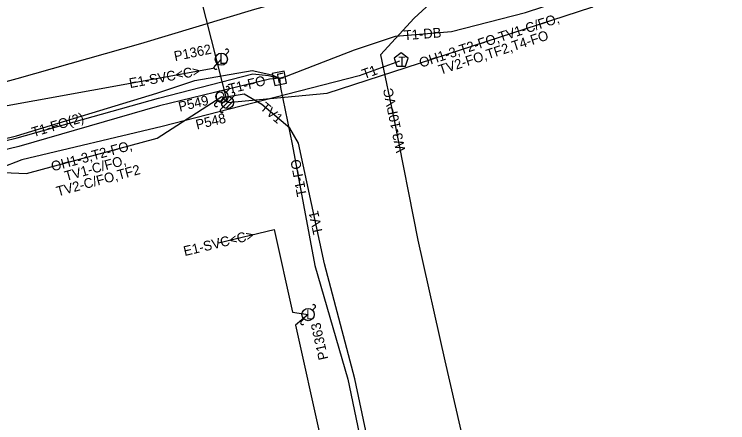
# Model space of a CAD drawing. Extents: x 2336688 to 2352634, y 362473 to 369571.
# Drawn here: x 2348250.9 to 2348543.2, y 367383.7 to 367551 of the extents above; entities that cross this region are included whole.
import ezdxf

# ---------------------------------------------------------------- set-up
doc = ezdxf.new("R2010")
doc.units = 0
for name, color, linetype in [('RD_EX_DV_Prop', 7, 'Continuous'), ('RD_EX_DV_TX_Prop', 7, 'Continuous'), ('RD_EX_RW', 7, 'Continuous'), ('RD_EX_RW_TX', 7, 'Continuous'), ('RD_HC_Data_Tic', 7, 'Continuous'), ('RD_PD_CstnLmt', 7, 'Continuous'), ('RD_PD_Final_TrvlWay', 7, 'Continuous'), ('RD_PD_PatLn4', 7, 'Continuous'), ('RD_SHT_ShtClip', 7, 'Continuous'), ('RD_Sketch2', 7, 'Continuous')]:
    doc.layers.add(name, color=color, linetype=linetype)

msp = doc.modelspace()

# ---------------------------------------------------------------- linework, layer by layer
at = {"layer": 'RD_EX_RW_TX'}
for points in [[(2348359.53, 367524.74), (2348362.5, 367525.55), (2348390.35, 367536.41), (2348407.13, 367542.05), (2348430.08, 367543.86), (2348460.37, 367551.68), (2348518.82, 367570.97), (2348539.75, 367577.27)], [(2348408.72, 367531.76), (2348392.21, 367525.78), (2348357.71, 367516.89), (2348311.55, 367505.03), (2348253.93, 367491.37), (2348226.44, 367480.77)], [(2348206.38, 367490.17), (2348251.79, 367501.21), (2348309.34, 367518.63), (2348324.84, 367523.82), (2348348.43, 367527.96), (2348356.39, 367526.21), (2348359.53, 367524.74), (2348359.93, 367520.91), (2348364.81, 367497.75), (2348374.05, 367448.12), (2348387.55, 367401.49), (2348397.52, 367353.79)], [(2348359.53, 367524.74), (2348355.51, 367524.43), (2348310.45, 367513.44), (2348252.78, 367496.75), (2348207.14, 367485.87), (2348156.56, 367475.89), (2348137.31, 367470.75), (2348134.76, 367458.49), (2348133.52, 367438.68), (2348140.76, 367386.86)], [(2348209.5, 367456.28), (2348210.32, 367458.48), (2348208.63, 367474.37), (2348207.08, 367489.5), (2348252.08, 367500.34), (2348310.01, 367516.64), (2348348.6, 367526.57), (2348355.1, 367525.87), (2348359.53, 367524.74)], [(2348400.57, 367353.94), (2348390.4, 367401.66), (2348378.01, 367448.82), (2348367.38, 367498.18), (2348363.76, 367504.36), (2348352.34, 367514.01), (2348345.04, 367518.21), (2348337.62, 367517), (2348338.28, 367514.83)]]:
    msp.add_lwpolyline(points, dxfattribs=at)
for points in [[(2348409.46, 367535.1), (2348406.61, 367533.03), (2348407.7, 367529.68), (2348411.22, 367529.68), (2348412.31, 367533.03)], [(2348361.48, 367527.69), (2348356.58, 367526.68), (2348357.59, 367521.78), (2348362.49, 367522.79)]]:
    msp.add_lwpolyline(points, close=True, dxfattribs=at)
at = {"layer": 'RD_HC_Data_Tic'}
for p, q in [((2348337.5, 367534.34), (2348338.56, 367535.4)), ((2348332.9, 367529.74), (2348333.96, 367530.8)), ((2348338.81, 367520.09), (2348337.75, 367519.02)), ((2348334.22, 367515.49), (2348333.16, 367514.43)), ((2348338.93, 367517.24), (2348335.86, 367514.18)), ((2348340.05, 367516.6), (2348336.51, 367513.06)), ((2348340.69, 367515.48), (2348337.63, 367512.41)), ((2348341.11, 367517.66), (2348340.05, 367516.6)), ((2348336.51, 367513.06), (2348335.45, 367512)), ((2348373.05, 367429.74), (2348374.11, 367430.8)), ((2348368.45, 367425.14), (2348369.51, 367426.2))]:
    msp.add_line(p, q, dxfattribs=at)
for centre in [(2348335.73, 367532.57), (2348335.99, 367517.26), (2348338.28, 367514.83), (2348371.28, 367427.97)]:
    msp.add_circle(centre, 2.5, dxfattribs=at)
for centre, start, end in [((2348338.03, 367535.93), 315, 135), ((2348333.43, 367529.21), 135, 315), ((2348338.28, 367520.62), 315, 135), ((2348340.58, 367518.19), 315, 135), ((2348333.69, 367513.9), 135, 315), ((2348335.98, 367511.47), 135, 315), ((2348373.58, 367431.33), 315, 135), ((2348368.98, 367424.61), 135, 315)]:
    msp.add_arc(centre, 0.75, start, end, dxfattribs=at)
at = {"layer": 'RD_PD_Final_TrvlWay'}
for points in [[(2348085.42, 367455.46), (2348069.9, 367482.21), (2348074.61, 367480.08), (2348206.15, 367506.02), (2348207.03, 367509.26), (2348209.48, 367506.65), (2348332.4, 367528.92), (2348335.73, 367532.57)], [(2348334.56, 367457.38), (2348357.39, 367462.88), (2348364.93, 367428.99), (2348371.28, 367427.97), (2348366.1, 367423.71), (2348386.64, 367331.4), (2348390.5, 367330.62), (2348387.22, 367328.8), (2348383.03, 367308.02)]]:
    msp.add_lwpolyline(points, dxfattribs=at)
at = {"layer": 'RD_SHT_ShtClip'}
for q in [(2348302.69, 367654.16), (2348335.99, 367517.26)]:
    msp.add_line((2348338.28, 367514.83), q, dxfattribs=at)
for points in [[(2348338.28, 367514.83), (2348379.11, 367518.63), (2348487.57, 367553.93), (2348522.81, 367574.9)], [(2348224.48, 367487.16), (2348255.92, 367485.8), (2348309.5, 367500.26), (2348335.99, 367517.26)]]:
    msp.add_lwpolyline(points, dxfattribs=at)
at = {"layer": 'RD_Sketch2'}
for points in [[(2348204.32, 367511.65), (2348252.13, 367524.59), (2348302.77, 367538.93), (2348349.4, 367552.98), (2348399.28, 367566.78), (2348419.19, 367573.03), (2348448.96, 367582.56), (2348495.7, 367596.69), (2348520.67, 367604.71), (2348535.97, 367592.48), (2348556.39, 367599.86), (2348601.65, 367616.49)], [(2348419.19, 367573.03), (2348421.47, 367566.58), (2348424.48, 367558.37), (2348414.74, 367549.36), (2348401.01, 367534.36), (2348406.6, 367507.53), (2348416.22, 367458.49), (2348427.29, 367409.06), (2348435.75, 367372.22)]]:
    msp.add_lwpolyline(points, dxfattribs=at)

# ---------------------------------------------------------------- texts
at = {"layer": 'RD_EX_DV_Prop'}
for rotation, p in [(10.2677, (2348298.33, 367520.71)), (13.57, (2348320.74, 367451.92))]:
    msp.add_text('E1-SVC<C>', height=4, rotation=rotation, dxfattribs=at).set_placement(p)
at = {"layer": 'RD_EX_DV_TX_Prop'}
for s, rotation, p in [('P1362', 11.5862, (2348316.77, 367531.76)), ('P549', 13.4802, (2348318.69, 367511.07)), ('P548', 13.4802, (2348325.76, 367503.73)), ('P1363', 102.542, (2348379.58, 367409.88))]:
    msp.add_text(s, height=4, rotation=rotation, dxfattribs=at).set_placement(p)
at = {"layer": 'RD_EX_RW'}
for s, rotation, p in [('T1-DB', 4.5062, (2348410.64, 367540.32)), ('T1', 19.8997, (2348394.21, 367524.38)), ('T1-FO', 13.7156, (2348339.18, 367518.39)), ('TV1', 319.7902, (2348351.34, 367512.24)), ('T1-FO(2)', 16.8473, (2348258.72, 367500.61)), ('T1-FO', 100.5445, (2348370.77, 367476.69)), ('TV1', 102.1548, (2348377.39, 367461.21))]:
    msp.add_text(s, height=4, rotation=rotation, dxfattribs=at).set_placement(p)
at = {"layer": 'RD_EX_RW_TX'}
msp.add_text('T', height=3.75, dxfattribs=at).set_placement((2348408.23, 367529.88))
msp.add_text('F', height=4, rotation=11.6664, dxfattribs=at).set_placement((2348358.83, 367522.55))
at = {"layer": 'RD_HC_Data_Tic'}
for s, rotation, p in [('L', 360, (2348334.92, 367530.64)), ('O', 180, (2348337.28, 367519.26)), ('L', 360, (2348370.47, 367426.03))]:
    msp.add_text(s, height=4, rotation=rotation, dxfattribs=at).set_placement(p)
at = {"layer": 'RD_PD_CstnLmt'}
msp.add_text('W3-10PVC', height=4, rotation=101.7679, dxfattribs=at).set_placement((2348411.29, 367494.83))
at = {"layer": 'RD_PD_PatLn4'}
for s, rotation, p in [('OH1-3,T2-FO,TV1-C/FO,', 18.0321, (2348417.56, 367529.04)), ('TV2-FO,TF2,T4-FO', 18.0321, (2348425.51, 367526.15)), ('OH1-3,T2-FO,', 15.1654, (2348266.59, 367486.58)), ('TV1-C/FO,', 15.1654, (2348272.09, 367482.68)), ('TV2-C/FO,TF2', 15.1654, (2348268.74, 367476.37))]:
    msp.add_text(s, height=4, rotation=rotation, dxfattribs=at).set_placement(p)

doc.saveas('drawing.dxf')
